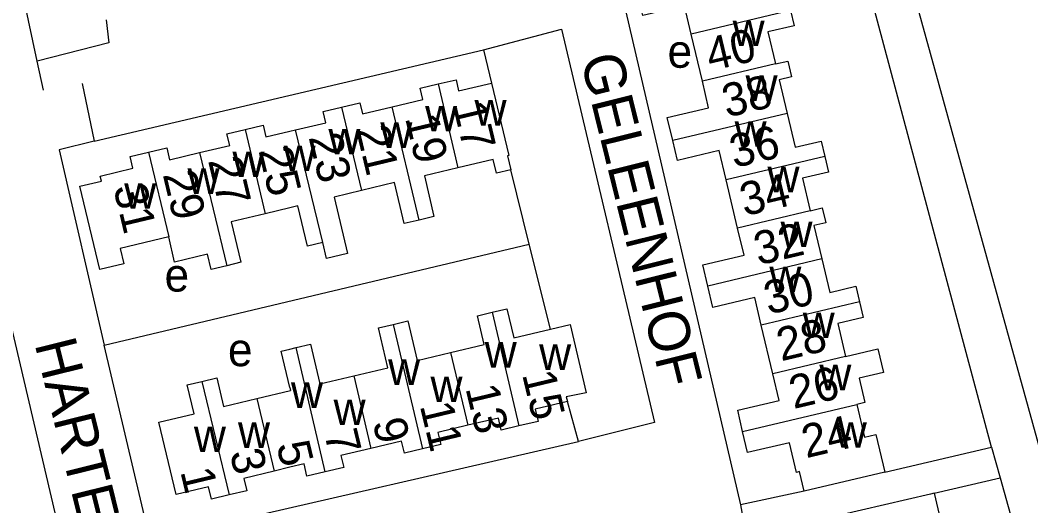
# Model space of a CAD drawing. Extents: x 157646 to 159241, y 379213 to 381217.
# Drawn here: x 158967.4 to 159089.5, y 380816.2 to 380874.9 of the extents above; entities that cross this region are included whole.
import ezdxf

# ---------------------------------------------------------------- set-up
doc = ezdxf.new("R2010")
doc.units = 0
for name, color, linetype in [('BLT_Basislijn', 7, 'Continuous'), ('BLT_Bebouwing', 7, 'Continuous'), ('BLT_Centroide', 7, 'Continuous'), ('BLT_Huisnummer', 7, 'Continuous'), ('BLT_Huisnummer_ tussenligend', 7, 'Continuous'), ('BLT_Onderverdeling_panden', 7, 'Continuous'), ('BLT_Straatnaam', 7, 'Continuous')]:
    doc.layers.add(name, color=color, linetype=linetype)

msp = doc.modelspace()

# ---------------------------------------------------------------- linework, layer by layer
at = {"layer": 'BLT_Basislijn'}
for p, q in [((159034.75, 380900.98), (159054.42, 380816.35)), ((159084.78, 380823.3), (159066.79, 380890.38)), ((158976.35, 380860.26), (159023.38, 380871.3)), ((159023.38, 380871.3), (159024.35, 380867.27)), ((158970.23, 380866.41), (158969.46, 380869.92)), ((158974.9, 380867.2), (158976.35, 380860.26)), ((159028.92, 380847.82), (159026.7, 380856.79)), ((158977.53, 380835.61), (159028.92, 380847.82)), ((159031.47, 380837.56), (159028.92, 380847.82)), ((158983.11, 380812.15), (158977.53, 380835.61)), ((159034.87, 380824), (159033.52, 380828.84)), ((158983.11, 380812.15), (159034.87, 380824)), ((159071.88, 380820.31), (159084.78, 380823.3)), ((159084.78, 380823.3), (159085.81, 380819.61)), ((159077.86, 380817.75), (159085.81, 380819.61)), ((159062.14, 380818), (159054.42, 380816.35)), ((159077.86, 380817.75), (159079.36, 380811.37)), ((159054.42, 380816.35), (159055.16, 380812.49))]:
    msp.add_line(p, q, dxfattribs=at)
for points in [[(159071.61, 380891.71), (159098.09, 380795.96), (159099.25, 380793.36), (159118.39, 380801.95)], [(158969.46, 380869.92), (158967.87, 380877.27), (158966.12, 380881.08), (158963.78, 380883.86), (158961.67, 380885.68), (158958.02, 380887.53)], [(158950.45, 380874.83), (158953.9, 380875.15), (158955.51, 380874.99), (158957.69, 380873.05), (158958.48, 380871.06), (158973.83, 380805.75)], [(158977.78, 380874.89), (158978.11, 380872.12), (158969.46, 380869.92)], [(159023.38, 380871.3), (159032.82, 380873.76), (159044.04, 380826.28), (159034.87, 380824)], [(158976.35, 380860.26), (158972.12, 380859.21), (158977.53, 380835.61)], [(159085.81, 380819.61), (159092.6, 380795.38), (159096.65, 380780.35)], [(159077.86, 380817.75), (159077.39, 380817.64), (159055.16, 380812.49)]]:
    msp.add_lwpolyline(points, dxfattribs=at)
at = {"layer": 'BLT_Bebouwing'}
for p, q in [((159049.83, 380867.49), (159048.48, 380873.18)), ((159000, 380861.47), (159000.66, 380861.62)), ((159054.09, 380849.77), (159052.72, 380855.57)), ((159000, 380852.21), (158997, 380851.49)), ((159058.34, 380832.17), (159056.95, 380838.05)), ((159000, 380835.16), (159000.73, 380835.33)), ((159000, 380830.51), (159000.08, 380830.17)), ((158995.99, 380829.18), (159000.08, 380830.17)), ((158999.99, 380820.89), (158998.08, 380820.43))]:
    msp.add_line(p, q, dxfattribs=at)
for points in [[(159048.48, 380873.18), (159047.67, 380876.61), (159042.62, 380875.41), (159042.04, 380877.88)], [(159060.47, 380876.02), (159060.91, 380874.18), (159057.76, 380873.44), (159058.68, 380869.58)], [(159058.68, 380869.58), (159060.14, 380869.93), (159060.6, 380868.01), (159059.12, 380867.66), (159060.09, 380863.59)], [(159012.35, 380864.4), (159016.04, 380865.28), (159015.72, 380866.64), (159017.89, 380867.16)], [(159017.89, 380867.16), (159020.06, 380867.67), (159020.38, 380866.32), (159024.35, 380867.27)], [(159024.35, 380867.27), (159026.43, 380858.51), (159026.3, 380858.48), (159026.7, 380856.79)], [(159046.25, 380860.32), (159045.59, 380863.1), (159050.59, 380864.28), (159049.83, 380867.49)], [(159006.23, 380864.38), (159008.43, 380864.9), (159008.76, 380863.54), (159012.35, 380864.4)], [(159000.66, 380861.62), (159004.35, 380862.47), (159004.02, 380863.85), (159006.23, 380864.38)], [(159060.09, 380863.59), (159061.05, 380859.52), (159064.2, 380860.27), (159064.64, 380858.39)], [(158994.57, 380861.65), (158996.76, 380862.18), (158997.1, 380860.77), (159000, 380861.47)], [(158989.08, 380858.88), (158992.71, 380859.74), (158992.38, 380861.13), (158994.57, 380861.65)], [(159052.72, 380855.57), (159051.88, 380859.12), (159046.82, 380857.92), (159046.25, 380860.32)], [(158985.34, 380848.71), (158979.48, 380847.31), (158979.93, 380845.45), (158977.01, 380844.75), (158974.6, 380854.82), (158977.21, 380855.44), (158977.06, 380856.04), (158981.02, 380856.99), (158980.68, 380858.4), (158982.89, 380858.93)], [(158982.89, 380858.93), (158985.11, 380859.46), (158985.45, 380858.01), (158989.08, 380858.88)], [(159026.7, 380856.79), (159024.96, 380856.38), (159024.56, 380858.04), (159020.3, 380857.03)], [(159064.64, 380858.39), (159065.08, 380856.52), (159061.94, 380855.78), (159062.87, 380851.85)], [(159020.3, 380857.03), (159016.24, 380856.06), (159017.4, 380851.15), (159015.61, 380850.73)], [(159015.61, 380850.73), (159013.81, 380850.3), (159012.64, 380855.25), (159008.63, 380854.29)], [(159008.63, 380854.29), (159005.32, 380853.5), (159006.94, 380846.69), (159004.41, 380846.09), (159003.95, 380848.01)], [(159003.95, 380848.01), (159002.11, 380847.57), (159000.95, 380852.43), (159000, 380852.21)], [(158997, 380851.49), (158992.88, 380850.51), (158994.05, 380845.63), (158992.35, 380845.22)], [(159062.87, 380851.85), (159064.32, 380852.19), (159064.74, 380850.41), (159063.32, 380850.07), (159064.28, 380846.04)], [(158992.35, 380845.22), (158990.49, 380844.78), (158990.05, 380846.61), (158986.04, 380845.66), (158985.34, 380848.71)], [(159050.48, 380842.77), (159049.87, 380845.31), (159054.87, 380846.49), (159054.09, 380849.77)], [(159064.28, 380846.04), (159065.23, 380842), (159068.37, 380842.74), (159068.81, 380840.86)], [(159056.95, 380838.05), (159056.16, 380841.39), (159051.09, 380840.19), (159050.48, 380842.77)], [(159068.81, 380840.86), (159069.26, 380838.97), (159066.19, 380838.24), (159067.14, 380834.25)], [(159019.41, 380834.74), (159023.46, 380835.7), (159022.64, 380839.18), (159024.43, 380839.6)], [(159024.43, 380839.6), (159026.22, 380840.02), (159027.05, 380836.51), (159031.47, 380837.56)], [(159007.71, 380831.94), (159011.83, 380832.91), (159010.7, 380837.72), (159012.47, 380838.14)], [(159012.47, 380838.14), (159014.25, 380838.56), (159015.37, 380833.79), (159019.41, 380834.74)], [(159031.47, 380837.56), (159033.86, 380838.12)], [(159033.86, 380838.12), (159035.8, 380829.87), (159033.39, 380829.39), (159033.52, 380828.84)], [(159000.73, 380835.33), (159002.47, 380835.75), (159003.6, 380830.97), (159007.71, 380831.94)], [(159000, 380830.51), (158998.95, 380834.91), (159000, 380835.16)], [(159067.14, 380834.25), (159071.03, 380835.17), (159071.71, 380832.32), (159068.79, 380831.63), (159069.48, 380828.71), (159068.51, 380828.48)], [(158989.36, 380831.25), (158991.15, 380831.68), (158991.98, 380828.23), (158995.99, 380829.18)], [(159054.7, 380825.21), (159054.1, 380827.77), (159059.1, 380828.95), (159058.34, 380832.17)], [(158992.64, 380817.55), (158990.52, 380817.04), (158990.16, 380818.53), (158986.24, 380817.59), (158984.15, 380826.33), (158988.4, 380827.35), (158987.57, 380830.82), (158989.36, 380831.25)], [(159033.52, 380828.84), (159029.63, 380827.92), (159029.98, 380826.42), (159027.66, 380825.87)], [(159068.51, 380828.48), (159069.44, 380824.52), (159070.81, 380824.84), (159071.88, 380820.31)], [(159027.66, 380825.87), (159025.53, 380825.37), (159025.19, 380826.82), (159021.49, 380825.95)], [(159021.49, 380825.95), (159017.87, 380825.09), (159018.22, 380823.62), (159016.01, 380823.1)], [(159062.14, 380818), (159061.58, 380820.36), (159061.19, 380820.27), (159060.35, 380823.85), (159055.3, 380822.66), (159054.7, 380825.21)], [(159009.78, 380823.16), (159006.15, 380822.3), (159006.49, 380820.86), (159004.27, 380820.34)], [(159016.01, 380823.1), (159013.83, 380822.59), (159013.49, 380824.03), (159009.78, 380823.16)], [(159004.27, 380820.34), (159002.05, 380819.81), (159001.7, 380821.29), (158999.99, 380820.89)], [(158998.08, 380820.43), (158994.42, 380819.55), (158994.78, 380818.06), (158992.64, 380817.55)], [(159071.88, 380820.31), (159062.14, 380818)]]:
    msp.add_lwpolyline(points, dxfattribs=at)
at = {"layer": 'BLT_Onderverdeling_panden'}
for p, q in [((159060.47, 380876.02), (159048.48, 380873.18)), ((159058.68, 380869.58), (159049.83, 380867.49)), ((159017.89, 380867.16), (159020.3, 380857.03)), ((159006.23, 380864.38), (159008.63, 380854.29)), ((159015.61, 380850.73), (159012.35, 380864.4)), ((159060.09, 380863.59), (159046.25, 380860.32)), ((158994.57, 380861.65), (158997, 380851.49)), ((159003.95, 380848.01), (159000.66, 380861.62)), ((158982.89, 380858.93), (158985.34, 380848.71)), ((158989.08, 380858.88), (158992.35, 380845.22)), ((159064.64, 380858.39), (159052.72, 380855.57)), ((159062.87, 380851.85), (159054.09, 380849.77)), ((159064.28, 380846.04), (159050.48, 380842.77)), ((159068.81, 380840.86), (159056.95, 380838.05)), ((159024.43, 380839.6), (159027.66, 380825.87)), ((159012.47, 380838.14), (159016.01, 380823.1)), ((159004.27, 380820.34), (159000.73, 380835.33)), ((159019.41, 380834.74), (159021.49, 380825.95)), ((159067.14, 380834.25), (159058.34, 380832.17)), ((159007.71, 380831.94), (159009.78, 380823.16)), ((158989.36, 380831.25), (158992.64, 380817.55)), ((158995.99, 380829.18), (158998.08, 380820.43)), ((159054.7, 380825.21), (159068.51, 380828.48))]:
    msp.add_line(p, q, dxfattribs=at)

# ---------------------------------------------------------------- texts
at = {"layer": 'BLT_Centroide'}
for s, p in [('w', (159053.49, 380871.75)), ('e', (159045.62, 380869.12)), ('w', (159055.05, 380865.12)), ('w', (159022.3, 380862.14)), ('w', (159016.33, 380861.44)), ('w', (159010.92, 380859.45)), ('w', (159053.73, 380859.59)), ('w', (159004.64, 380858.67)), ('w', (158999.23, 380856.66)), ('w', (158993.05, 380855.92)), ('w', (158987.62, 380853.89)), ('w', (159057.7, 380854.09)), ('w', (158979.97, 380852.09)), ('w', (159059.28, 380847.47)), ('e', (158984.84, 380842.1)), ('w', (159057.93, 380842.03)), ('w', (159061.96, 380836.5)), ('e', (158992.5, 380833.09)), ('w', (159023.53, 380832.92)), ('w', (159030.11, 380832.64)), ('w', (159011.86, 380830.83)), ('w', (159063.97, 380830.19)), ('w', (159016.98, 380828.75)), ('w', (159000.12, 380828.05)), ('w', (159005.27, 380825.97)), ('w', (158988.39, 380822.72)), ('w', (158993.72, 380823.23)), ('w', (159065.84, 380823.25))]:
    msp.add_text(s, height=4, dxfattribs=at).set_placement(p)
at = {"layer": 'BLT_Huisnummer'}
for s, rotation, p in [('40', 13.3055, (159050.8, 380868.69)), ('17', 283.3955, (159019.66, 380864.6)), ('21', 283.3955, (159007.96, 380861.68)), ('36', 13.3055, (159053.67, 380857)), ('25', 283.3955, (158996.17, 380859.13)), ('31', 283.3955, (158978.63, 380854.66)), ('32', 13.3055, (159056.6, 380845.25)), ('28', 13.3055, (159059.34, 380833.67)), ('15', 283.4595, (159028.03, 380832.11)), ('9', 283.4595, (159009.96, 380826.36)), ('24', 13.3055, (159062.37, 380821.97)), ('5', 283.4595, (158998.34, 380823.6)), ('1', 283.4595, (158986.73, 380820.39))]:
    msp.add_text(s, height=4, rotation=rotation, dxfattribs=at).set_placement(p)
at = {"layer": 'BLT_Huisnummer_ tussenligend'}
for s, rotation, p in [('38', 13.3055, (159052.76, 380863.09)), ('19', 283.3955, (159013.89, 380863.07)), ('23', 283.3955, (159002.23, 380860.75)), ('27', 283.3955, (158990.08, 380857.93)), ('29', 283.3955, (158984.61, 380856.25)), ('34', 13.3055, (159054.91, 380851.18)), ('30', 13.3055, (159057.81, 380839.3)), ('26', 13.3055, (159060.85, 380827.91)), ('13', 283.4595, (159021.19, 380830.44)), ('11', 283.4595, (159015.67, 380828.33)), ('7', 283.4595, (159004.11, 380824.99)), ('3', 283.4595, (158992.7, 380822.65))]:
    msp.add_text(s, height=4, rotation=rotation, dxfattribs=at).set_placement(p)
at = {"layer": 'BLT_Straatnaam'}
for s, rotation, p in [('GELEENHOF', 283.9402, (159035.08, 380870.23)), ('HARTELSTEIN', 283.9525, (158969.12, 380835.8))]:
    msp.add_text(s, height=5, rotation=rotation, dxfattribs=at).set_placement(p)

doc.saveas('drawing.dxf')
